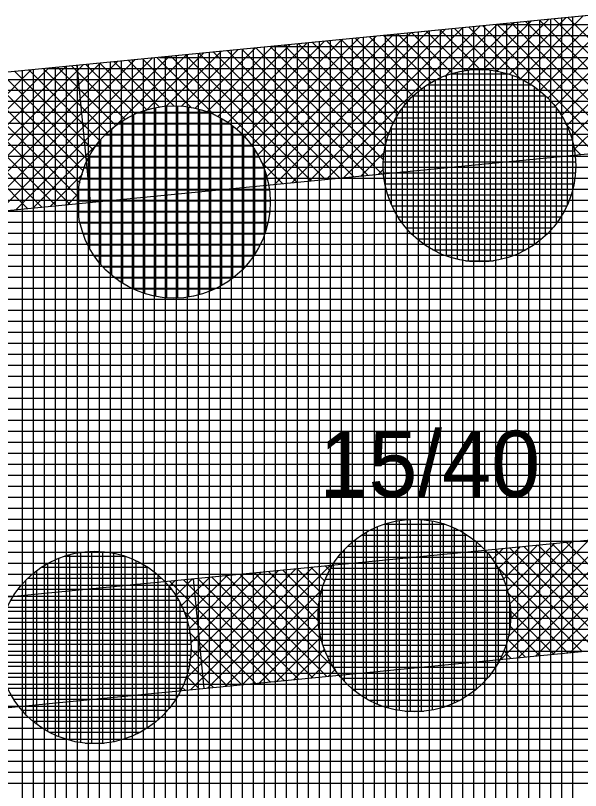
# Model space of a CAD drawing. Extents: x -566461 to -565198, y -1096301 to -1095707.
# Drawn here: x -566346.81 to -566336.54, y -1095854.4 to -1095840.31 of the extents above; entities that cross this region are included whole.
import ezdxf

# ---------------------------------------------------------------- set-up
doc = ezdxf.new("R2010")
doc.units = 0
for name, color, linetype in [('Vrstva 1', 7, 'Continuous'), ('Vrstva 40', 7, 'Continuous'), ('Vrstva 41', 7, 'Continuous'), ('Vrstva 42', 7, 'Continuous'), ('Vrstva 43', 7, 'Continuous'), ('Vrstva 44', 7, 'Continuous')]:
    doc.layers.add(name, color=color, linetype=linetype)

msp = doc.modelspace()

# ---------------------------------------------------------------- linework, layer by layer
at = {"layer": 'Vrstva 1'}
msp.add_line((-566305.22, -1095837.26), (-566355.65, -1095842.19), dxfattribs=at)
at = {"layer": 'Vrstva 41'}
for p, q in [((-566333.984, -1095840.072), (-566336.664, -1095842.752)), ((-566335.551, -1095840.225), (-566337.143, -1095841.817)), ((-566335.238, -1095840.195), (-566337.011, -1095841.967)), ((-566334.924, -1095840.164), (-566336.895, -1095842.134)), ((-566334.611, -1095840.133), (-566336.796, -1095842.318)), ((-566334.297, -1095840.103), (-566336.717, -1095842.523)), ((-566336.805, -1095840.348), (-566337.841, -1095841.383)), ((-566336.492, -1095840.317), (-566337.64, -1095841.465)), ((-566336.178, -1095840.286), (-566337.457, -1095841.565)), ((-566335.865, -1095840.256), (-566337.292, -1095841.683)), ((-566337.03, -1095840.37), (-566334.742, -1095842.658)), ((-566336.772, -1095840.344), (-566334.631, -1095842.486)), ((-566338.373, -1095840.501), (-566341.156, -1095843.285)), ((-566338.059, -1095840.47), (-566339.006, -1095841.417)), ((-566337.746, -1095840.44), (-566338.624, -1095841.318)), ((-566337.432, -1095840.409), (-566338.324, -1095841.301)), ((-566338.318, -1095840.496), (-566336.03, -1095842.784)), ((-566337.119, -1095840.378), (-566338.069, -1095841.328)), ((-566338.06, -1095840.47), (-566335.772, -1095842.758)), ((-566337.803, -1095840.445), (-566335.515, -1095842.733)), ((-566337.545, -1095840.42), (-566335.257, -1095842.708)), ((-566337.287, -1095840.395), (-566334.999, -1095842.683)), ((-566339.94, -1095840.654), (-566342.323, -1095843.037)), ((-566339.627, -1095840.624), (-566342.252, -1095843.249)), ((-566339.313, -1095840.593), (-566342.097, -1095843.377)), ((-566339, -1095840.562), (-566341.783, -1095843.346)), ((-566338.686, -1095840.532), (-566341.47, -1095843.315)), ((-566339.864, -1095840.647), (-566339.069, -1095841.442)), ((-566339.606, -1095840.622), (-566338.86, -1095841.368)), ((-566339.348, -1095840.596), (-566338.627, -1095841.318)), ((-566339.091, -1095840.571), (-566338.363, -1095841.299)), ((-566338.833, -1095840.546), (-566338.048, -1095841.331)), ((-566338.575, -1095840.521), (-566337.622, -1095841.475)), ((-566341.194, -1095840.777), (-566342.798, -1095842.381)), ((-566340.881, -1095840.746), (-566342.654, -1095842.519)), ((-566340.567, -1095840.716), (-566342.525, -1095842.673)), ((-566340.254, -1095840.685), (-566342.415, -1095842.846)), ((-566341.152, -1095840.773), (-566339.836, -1095842.089)), ((-566340.894, -1095840.748), (-566339.716, -1095841.926)), ((-566340.637, -1095840.722), (-566339.58, -1095841.78)), ((-566340.379, -1095840.697), (-566339.427, -1095841.649)), ((-566340.121, -1095840.672), (-566339.257, -1095841.536)), ((-566342.762, -1095840.93), (-566343.799, -1095841.967)), ((-566342.448, -1095840.899), (-566343.551, -1095842.002)), ((-566342.135, -1095840.869), (-566343.333, -1095842.067)), ((-566341.821, -1095840.838), (-566343.137, -1095842.154)), ((-566341.508, -1095840.807), (-566342.959, -1095842.259)), ((-566342.698, -1095840.924), (-566340.41, -1095843.212)), ((-566342.44, -1095840.899), (-566340.152, -1095843.186)), ((-566342.183, -1095840.873), (-566340.116, -1095842.94)), ((-566341.925, -1095840.848), (-566340.086, -1095842.688)), ((-566341.667, -1095840.823), (-566340.023, -1095842.467)), ((-566341.41, -1095840.798), (-566339.939, -1095842.269)), ((-566344.016, -1095841.053), (-566346.799, -1095843.836)), ((-566343.702, -1095841.022), (-566345.056, -1095842.376)), ((-566343.389, -1095840.991), (-566344.433, -1095842.036)), ((-566344.244, -1095841.075), (-566343.195, -1095842.124)), ((-566343.075, -1095840.961), (-566344.083, -1095841.968)), ((-566343.986, -1095841.05), (-566341.698, -1095843.338)), ((-566343.729, -1095841.025), (-566341.441, -1095843.312)), ((-566343.471, -1095840.999), (-566341.183, -1095843.287)), ((-566343.213, -1095840.974), (-566340.925, -1095843.262)), ((-566342.956, -1095840.949), (-566340.668, -1095843.237)), ((-566345.583, -1095841.206), (-566348.367, -1095843.989)), ((-566345.269, -1095841.175), (-566348.053, -1095843.959)), ((-566344.956, -1095841.145), (-566347.74, -1095843.928)), ((-566344.642, -1095841.114), (-566347.426, -1095843.898)), ((-566344.329, -1095841.083), (-566347.113, -1095843.867)), ((-566345.532, -1095841.201), (-566344.627, -1095842.106)), ((-566345.275, -1095841.176), (-566344.418, -1095842.032)), ((-566345.017, -1095841.151), (-566344.186, -1095841.981)), ((-566344.759, -1095841.125), (-566343.924, -1095841.96)), ((-566344.502, -1095841.1), (-566343.61, -1095841.991)), ((-566346.523, -1095841.298), (-566348.794, -1095843.568)), ((-566346.21, -1095841.267), (-566348.698, -1095843.755)), ((-566345.896, -1095841.236), (-566348.624, -1095843.964)), ((-566347.078, -1095841.352), (-566345.492, -1095842.938)), ((-566346.82, -1095841.327), (-566345.39, -1095842.757)), ((-566346.563, -1095841.302), (-566345.27, -1095842.594)), ((-566346.305, -1095841.276), (-566345.134, -1095842.447)), ((-566346.047, -1095841.251), (-566344.983, -1095842.316)), ((-566345.79, -1095841.226), (-566344.814, -1095842.202)), ((-566348.366, -1095841.478), (-566346.079, -1095843.766)), ((-566348.109, -1095841.453), (-566345.821, -1095843.741)), ((-566347.851, -1095841.428), (-566345.665, -1095843.613)), ((-566347.593, -1095841.402), (-566345.635, -1095843.36)), ((-566347.336, -1095841.377), (-566345.576, -1095843.137)), ((-566348.882, -1095841.528), (-566346.594, -1095843.816)), ((-566348.624, -1095841.503), (-566346.336, -1095843.791)), ((-566336.815, -1095842.282), (-566336.288, -1095842.809)), ((-566340.003, -1095842.414), (-566340.843, -1095843.254)), ((-566345.254, -1095842.574), (-566346.486, -1095843.806)), ((-566336.671, -1095842.708), (-566336.545, -1095842.834)), ((-566340.102, -1095842.796), (-566340.529, -1095843.223)), ((-566342.354, -1095842.965), (-566341.956, -1095843.363)), ((-566340.119, -1095843.096), (-566340.216, -1095843.193)), ((-566345.594, -1095843.197), (-566346.172, -1095843.775)), ((-566342.221, -1095843.38), (-566342.214, -1095843.388)), ((-566345.662, -1095843.547), (-566345.859, -1095843.744)), ((-566335.762, -1095849.791), (-566337.989, -1095852.019)), ((-566335.448, -1095849.76), (-566337.676, -1095851.988)), ((-566337.329, -1095849.944), (-566337.95, -1095850.565)), ((-566337.016, -1095849.913), (-566337.88, -1095850.777)), ((-566336.075, -1095849.822), (-566337.866, -1095851.613)), ((-566336.702, -1095849.883), (-566337.833, -1095851.014)), ((-566336.389, -1095849.852), (-566337.827, -1095851.291)), ((-566335.293, -1095849.887), (-566337.362, -1095851.957)), ((-566337.314, -1095849.943), (-566335.483, -1095851.774)), ((-566337.056, -1095849.917), (-566335.225, -1095851.748)), ((-566336.799, -1095849.892), (-566335.427, -1095851.264)), ((-566338.269, -1095850.036), (-566338.278, -1095850.045)), ((-566337.956, -1095850.005), (-566338.15, -1095850.2)), ((-566338.087, -1095850.018), (-566336.256, -1095851.849)), ((-566337.643, -1095849.975), (-566338.041, -1095850.373)), ((-566337.829, -1095849.993), (-566335.998, -1095851.824)), ((-566337.572, -1095849.968), (-566335.741, -1095851.799)), ((-566341.718, -1095850.373), (-566343.732, -1095852.387)), ((-566341.404, -1095850.342), (-566343.632, -1095852.57)), ((-566341.091, -1095850.312), (-566343.318, -1095852.539)), ((-566341.694, -1095850.371), (-566341.25, -1095850.815)), ((-566341.437, -1095850.346), (-566341.183, -1095850.599)), ((-566341.179, -1095850.32), (-566341.095, -1095850.404)), ((-566338.08, -1095850.308), (-566336.514, -1095851.874)), ((-566335.467, -1095850.345), (-566337.049, -1095851.927)), ((-566342.972, -1095850.496), (-566343.72, -1095851.244)), ((-566342.658, -1095850.465), (-566343.661, -1095851.468)), ((-566342.031, -1095850.404), (-566343.652, -1095852.024)), ((-566342.345, -1095850.434), (-566343.632, -1095851.721)), ((-566342.982, -1095850.497), (-566341.152, -1095852.328)), ((-566342.725, -1095850.472), (-566340.995, -1095852.202)), ((-566342.467, -1095850.446), (-566341.237, -1095851.677)), ((-566342.21, -1095850.421), (-566341.294, -1095851.336)), ((-566341.952, -1095850.396), (-566341.292, -1095851.056)), ((-566343.912, -1095850.588), (-566344.023, -1095850.698)), ((-566344.013, -1095850.597), (-566342.182, -1095852.428)), ((-566343.599, -1095850.557), (-566343.904, -1095850.862)), ((-566343.285, -1095850.526), (-566343.802, -1095851.043)), ((-566343.755, -1095850.572), (-566341.925, -1095852.403)), ((-566343.498, -1095850.547), (-566341.667, -1095852.378)), ((-566343.24, -1095850.522), (-566341.409, -1095852.353)), ((-566341.228, -1095850.732), (-566343.005, -1095852.509)), ((-566337.874, -1095850.797), (-566336.771, -1095851.9)), ((-566335.508, -1095850.668), (-566336.735, -1095851.896)), ((-566341.293, -1095851.08), (-566342.691, -1095852.478)), ((-566343.763, -1095851.13), (-566342.44, -1095852.454)), ((-566337.824, -1095851.129), (-566337.029, -1095851.925)), ((-566341.293, -1095851.362), (-566342.378, -1095852.447)), ((-566337.839, -1095851.398), (-566337.287, -1095851.95)), ((-566343.652, -1095851.524), (-566342.698, -1095852.479)), ((-566341.255, -1095851.608), (-566342.065, -1095852.417)), ((-566337.875, -1095851.645), (-566337.544, -1095851.975)), ((-566343.631, -1095851.828), (-566342.955, -1095852.504)), ((-566341.19, -1095851.825), (-566341.751, -1095852.386)), ((-566337.944, -1095851.859), (-566337.802, -1095852)), ((-566341.103, -1095852.021), (-566341.438, -1095852.356)), ((-566343.658, -1095852.084), (-566343.213, -1095852.529)), ((-566340.997, -1095852.198), (-566341.124, -1095852.325)), ((-566343.707, -1095852.317), (-566343.471, -1095852.554)), ((-566343.785, -1095852.523), (-566343.728, -1095852.579)), ((-566346.751, -1095852.86), (-566346.767, -1095852.876))]:
    msp.add_line(p, q, dxfattribs=at)
at = {"layer": 'Vrstva 42'}
for p, q in [((-566345.697, -1095841.217), (-566345.454, -1095843.705)), ((-566343.579, -1095850.555), (-566343.385, -1095852.546))]:
    msp.add_line(p, q, dxfattribs=at)
for points in [[(-566355.65, -1095842.19), (-566355.093, -1095844.647), (-566304.64, -1095839.715), (-566305.22, -1095837.26)], [(-566353.532, -1095851.528), (-566353.085, -1095853.494), (-566302.553, -1095848.555), (-566303.017, -1095846.59)]]:
    msp.add_lwpolyline(points, close=True, dxfattribs=at)
at = {"layer": 'Vrstva 43'}
for p, q in [((-566336.89, -1095840.356), (-566336.89, -1095861.195)), ((-566336.69, -1095840.336), (-566336.69, -1095861.18)), ((-566338.49, -1095840.512), (-566338.49, -1095861.319)), ((-566338.29, -1095840.493), (-566338.29, -1095861.303)), ((-566338.09, -1095840.473), (-566338.09, -1095861.288)), ((-566338.056, -1095840.47), (-566304.463, -1095840.47)), ((-566337.89, -1095840.454), (-566337.89, -1095861.272)), ((-566337.69, -1095840.434), (-566337.69, -1095861.257)), ((-566337.49, -1095840.415), (-566337.49, -1095861.242)), ((-566337.29, -1095840.395), (-566337.29, -1095861.226)), ((-566337.09, -1095840.376), (-566337.09, -1095861.211)), ((-566339.89, -1095840.649), (-566339.89, -1095861.427)), ((-566339.69, -1095840.63), (-566339.69, -1095861.411)), ((-566339.49, -1095840.61), (-566339.49, -1095861.396)), ((-566339.29, -1095840.591), (-566339.29, -1095861.38)), ((-566339.09, -1095840.571), (-566339.09, -1095861.365)), ((-566338.89, -1095840.552), (-566338.89, -1095861.35)), ((-566338.69, -1095840.532), (-566338.69, -1095861.334)), ((-566341.29, -1095840.786), (-566341.29, -1095861.535)), ((-566341.09, -1095840.767), (-566341.09, -1095861.519)), ((-566340.89, -1095840.747), (-566340.89, -1095861.504)), ((-566340.69, -1095840.728), (-566340.69, -1095861.488)), ((-566340.49, -1095840.708), (-566340.49, -1095861.473)), ((-566340.29, -1095840.688), (-566340.29, -1095861.457)), ((-566340.102, -1095840.67), (-566304.416, -1095840.67)), ((-566340.09, -1095840.669), (-566340.09, -1095861.442)), ((-566342.69, -1095840.923), (-566342.69, -1095861.642)), ((-566342.49, -1095840.903), (-566342.49, -1095861.627)), ((-566342.29, -1095840.884), (-566342.29, -1095861.612)), ((-566342.147, -1095840.87), (-566304.368, -1095840.87)), ((-566342.09, -1095840.864), (-566342.09, -1095861.596)), ((-566341.89, -1095840.845), (-566341.89, -1095861.581)), ((-566341.69, -1095840.825), (-566341.69, -1095861.565)), ((-566341.49, -1095840.806), (-566341.49, -1095861.55)), ((-566344.193, -1095841.07), (-566304.321, -1095841.07)), ((-566344.09, -1095841.06), (-566344.09, -1095861.75)), ((-566343.89, -1095841.04), (-566343.89, -1095861.735)), ((-566343.69, -1095841.021), (-566343.69, -1095861.72)), ((-566343.49, -1095841.001), (-566343.49, -1095861.704)), ((-566343.29, -1095840.982), (-566343.29, -1095861.689)), ((-566343.09, -1095840.962), (-566343.09, -1095861.673)), ((-566342.89, -1095840.943), (-566342.89, -1095861.658)), ((-566345.69, -1095841.216), (-566345.69, -1095861.874)), ((-566345.49, -1095841.197), (-566345.49, -1095861.858)), ((-566345.29, -1095841.177), (-566345.29, -1095861.843)), ((-566345.09, -1095841.158), (-566345.09, -1095861.827)), ((-566344.89, -1095841.138), (-566344.89, -1095861.812)), ((-566344.69, -1095841.119), (-566344.69, -1095861.797)), ((-566344.49, -1095841.099), (-566344.49, -1095861.781)), ((-566344.29, -1095841.079), (-566344.29, -1095861.766)), ((-566346.69, -1095841.314), (-566346.69, -1095861.951)), ((-566346.49, -1095841.295), (-566346.49, -1095861.935)), ((-566346.29, -1095841.275), (-566346.29, -1095861.92)), ((-566346.239, -1095841.27), (-566304.274, -1095841.27)), ((-566346.09, -1095841.255), (-566346.09, -1095861.905)), ((-566345.89, -1095841.236), (-566345.89, -1095861.889)), ((-566348.285, -1095841.47), (-566304.227, -1095841.47)), ((-566350.331, -1095841.67), (-566304.18, -1095841.67)), ((-566352.377, -1095841.87), (-566304.132, -1095841.87)), ((-566354.423, -1095842.07), (-566304.085, -1095842.07)), ((-566355.632, -1095842.27), (-566304.038, -1095842.27)), ((-566355.586, -1095842.47), (-566303.991, -1095842.47)), ((-566355.541, -1095842.67), (-566303.944, -1095842.67)), ((-566355.496, -1095842.87), (-566303.897, -1095842.87)), ((-566355.45, -1095843.07), (-566303.849, -1095843.07)), ((-566355.405, -1095843.27), (-566303.802, -1095843.27)), ((-566355.36, -1095843.47), (-566303.755, -1095843.47)), ((-566355.314, -1095843.67), (-566303.708, -1095843.67)), ((-566355.269, -1095843.87), (-566303.661, -1095843.87)), ((-566355.223, -1095844.07), (-566303.613, -1095844.07)), ((-566355.178, -1095844.27), (-566303.566, -1095844.27)), ((-566355.133, -1095844.47), (-566303.519, -1095844.47)), ((-566355.087, -1095844.67), (-566303.472, -1095844.67)), ((-566355.042, -1095844.87), (-566303.425, -1095844.87)), ((-566354.997, -1095845.07), (-566303.378, -1095845.07)), ((-566354.951, -1095845.27), (-566303.33, -1095845.27)), ((-566354.906, -1095845.47), (-566303.283, -1095845.47)), ((-566354.861, -1095845.67), (-566303.236, -1095845.67)), ((-566354.815, -1095845.87), (-566303.189, -1095845.87)), ((-566354.77, -1095846.07), (-566303.142, -1095846.07)), ((-566354.724, -1095846.27), (-566303.094, -1095846.27)), ((-566354.679, -1095846.47), (-566303.047, -1095846.47)), ((-566354.634, -1095846.67), (-566303, -1095846.67)), ((-566354.588, -1095846.87), (-566302.953, -1095846.87)), ((-566354.543, -1095847.07), (-566302.906, -1095847.07)), ((-566354.498, -1095847.27), (-566302.859, -1095847.27)), ((-566354.452, -1095847.47), (-566302.811, -1095847.47)), ((-566354.407, -1095847.67), (-566302.764, -1095847.67)), ((-566354.361, -1095847.87), (-566302.717, -1095847.87)), ((-566354.316, -1095848.07), (-566302.67, -1095848.07)), ((-566354.271, -1095848.27), (-566302.623, -1095848.27)), ((-566354.225, -1095848.47), (-566302.575, -1095848.47)), ((-566354.18, -1095848.67), (-566302.528, -1095848.67)), ((-566354.135, -1095848.87), (-566302.481, -1095848.87)), ((-566354.089, -1095849.07), (-566302.434, -1095849.07)), ((-566354.044, -1095849.27), (-566302.387, -1095849.27)), ((-566353.998, -1095849.47), (-566302.34, -1095849.47)), ((-566353.953, -1095849.67), (-566302.292, -1095849.67)), ((-566353.908, -1095849.87), (-566302.245, -1095849.87)), ((-566353.862, -1095850.07), (-566302.198, -1095850.07)), ((-566353.817, -1095850.27), (-566302.151, -1095850.27)), ((-566353.772, -1095850.47), (-566302.104, -1095850.47)), ((-566353.726, -1095850.67), (-566302.056, -1095850.67)), ((-566353.681, -1095850.87), (-566302.009, -1095850.87)), ((-566353.635, -1095851.07), (-566301.962, -1095851.07)), ((-566353.59, -1095851.27), (-566301.915, -1095851.27)), ((-566353.545, -1095851.47), (-566301.868, -1095851.47)), ((-566353.499, -1095851.67), (-566301.821, -1095851.67)), ((-566353.454, -1095851.87), (-566301.773, -1095851.87)), ((-566353.409, -1095852.07), (-566301.726, -1095852.07)), ((-566353.363, -1095852.27), (-566301.679, -1095852.27)), ((-566353.318, -1095852.47), (-566301.632, -1095852.47)), ((-566353.272, -1095852.67), (-566301.585, -1095852.67)), ((-566353.227, -1095852.87), (-566301.537, -1095852.87)), ((-566353.182, -1095853.07), (-566301.49, -1095853.07)), ((-566353.136, -1095853.27), (-566301.443, -1095853.27)), ((-566353.091, -1095853.47), (-566301.396, -1095853.47)), ((-566353.046, -1095853.67), (-566301.349, -1095853.67)), ((-566353, -1095853.87), (-566301.302, -1095853.87)), ((-566352.955, -1095854.07), (-566301.254, -1095854.07)), ((-566352.909, -1095854.27), (-566301.207, -1095854.27))]:
    msp.add_line(p, q, dxfattribs=at)
msp.add_lwpolyline([(-566355.65, -1095842.19), (-566351.09, -1095862.29), (-566300.24, -1095858.37), (-566305.22, -1095837.26)], close=True, dxfattribs=at)
at = {"layer": 'Vrstva 44'}
for p, q in [((-566338.78, -1095844.743), (-566338.78, -1095841.338)), ((-566338.58, -1095844.778), (-566338.58, -1095841.303)), ((-566338.38, -1095844.788), (-566338.38, -1095841.291)), ((-566338.18, -1095844.777), (-566338.18, -1095841.302)), ((-566337.98, -1095844.742), (-566337.98, -1095841.338)), ((-566339.18, -1095844.596), (-566339.18, -1095841.484)), ((-566338.98, -1095844.682), (-566338.98, -1095841.397)), ((-566338.898, -1095841.37), (-566337.858, -1095841.37)), ((-566337.78, -1095844.684), (-566337.78, -1095841.398)), ((-566337.58, -1095844.595), (-566337.58, -1095841.485)), ((-566339.38, -1095844.474), (-566339.38, -1095841.606)), ((-566339.328, -1095841.57), (-566337.432, -1095841.57)), ((-566337.38, -1095844.474), (-566337.38, -1095841.606)), ((-566339.583, -1095841.77), (-566337.178, -1095841.77)), ((-566339.58, -1095844.313), (-566339.58, -1095841.767)), ((-566337.18, -1095844.312), (-566337.18, -1095841.768)), ((-566344.46, -1095845.366), (-566344.46, -1095842.034)), ((-566344.26, -1095845.417), (-566344.26, -1095841.982)), ((-566344.06, -1095845.443), (-566344.06, -1095841.955)), ((-566343.86, -1095845.447), (-566343.86, -1095841.953)), ((-566343.66, -1095845.428), (-566343.66, -1095841.973)), ((-566343.46, -1095845.385), (-566343.46, -1095842.016)), ((-566339.78, -1095844.087), (-566339.78, -1095841.992)), ((-566339.763, -1095841.97), (-566336.998, -1095841.97)), ((-566336.98, -1095844.09), (-566336.98, -1095841.993)), ((-566344.66, -1095845.288), (-566344.66, -1095842.112)), ((-566344.589, -1095842.08), (-566343.27, -1095842.08)), ((-566343.26, -1095845.315), (-566343.26, -1095842.084)), ((-566343.06, -1095845.217), (-566343.06, -1095842.184)), ((-566339.897, -1095842.17), (-566336.863, -1095842.17)), ((-566344.95, -1095842.28), (-566342.91, -1095842.28)), ((-566344.86, -1095845.181), (-566344.86, -1095842.218)), ((-566342.86, -1095845.083), (-566342.86, -1095842.317)), ((-566339.98, -1095843.748), (-566339.98, -1095842.335)), ((-566336.78, -1095843.744), (-566336.78, -1095842.332)), ((-566345.182, -1095842.48), (-566342.677, -1095842.48)), ((-566345.06, -1095845.034), (-566345.06, -1095842.366)), ((-566339.995, -1095842.37), (-566336.765, -1095842.37)), ((-566345.26, -1095844.837), (-566345.26, -1095842.564)), ((-566342.66, -1095844.902), (-566342.66, -1095842.499)), ((-566340.064, -1095842.57), (-566336.696, -1095842.57)), ((-566345.351, -1095842.68), (-566342.51, -1095842.68)), ((-566342.46, -1095844.647), (-566342.46, -1095842.754)), ((-566345.474, -1095842.88), (-566342.385, -1095842.88)), ((-566345.46, -1095844.548), (-566345.46, -1095842.854)), ((-566340.109, -1095842.77), (-566336.653, -1095842.77)), ((-566340.128, -1095842.97), (-566336.632, -1095842.97)), ((-566345.565, -1095843.08), (-566342.296, -1095843.08)), ((-566342.26, -1095844.217), (-566342.26, -1095843.18)), ((-566340.123, -1095843.17), (-566336.635, -1095843.17)), ((-566345.629, -1095843.28), (-566342.233, -1095843.28)), ((-566345.66, -1095843.958), (-566345.66, -1095843.437)), ((-566340.097, -1095843.37), (-566336.663, -1095843.37)), ((-566345.665, -1095843.48), (-566342.194, -1095843.48)), ((-566340.046, -1095843.57), (-566336.714, -1095843.57)), ((-566345.678, -1095843.68), (-566342.181, -1095843.68)), ((-566345.669, -1095843.88), (-566342.191, -1095843.88)), ((-566339.97, -1095843.77), (-566336.791, -1095843.77)), ((-566339.86, -1095843.97), (-566336.899, -1095843.97)), ((-566345.637, -1095844.08), (-566342.224, -1095844.08)), ((-566339.715, -1095844.17), (-566337.046, -1095844.17)), ((-566345.58, -1095844.28), (-566342.28, -1095844.28)), ((-566339.514, -1095844.37), (-566337.245, -1095844.37)), ((-566345.494, -1095844.48), (-566342.364, -1095844.48)), ((-566339.226, -1095844.57), (-566337.535, -1095844.57)), ((-566345.378, -1095844.68), (-566342.483, -1095844.68)), ((-566345.22, -1095844.88), (-566342.638, -1095844.88)), ((-566338.634, -1095844.77), (-566338.124, -1095844.77)), ((-566345.005, -1095845.08), (-566342.856, -1095845.08)), ((-566344.678, -1095845.28), (-566343.179, -1095845.28)), ((-566339.83, -1095852.947), (-566339.83, -1095849.492)), ((-566339.63, -1095852.968), (-566339.63, -1095849.473)), ((-566339.43, -1095852.965), (-566339.43, -1095849.477)), ((-566339.23, -1095852.937), (-566339.23, -1095849.503)), ((-566340.23, -1095852.836), (-566340.23, -1095849.605)), ((-566340.108, -1095849.56), (-566339.01, -1095849.56)), ((-566340.03, -1095852.905), (-566340.03, -1095849.534)), ((-566339.03, -1095852.886), (-566339.03, -1095849.553)), ((-566338.83, -1095852.809), (-566338.83, -1095849.632)), ((-566340.522, -1095849.76), (-566338.596, -1095849.76)), ((-566340.43, -1095852.736), (-566340.43, -1095849.704)), ((-566338.63, -1095852.701), (-566338.63, -1095849.739)), ((-566340.63, -1095852.604), (-566340.63, -1095849.835)), ((-566338.43, -1095852.554), (-566338.43, -1095849.885)), ((-566345.62, -1095853.531), (-566345.62, -1095850.07)), ((-566345.42, -1095853.549), (-566345.42, -1095850.053)), ((-566345.22, -1095853.542), (-566345.22, -1095850.058)), ((-566345.02, -1095853.513), (-566345.02, -1095850.086)), ((-566340.83, -1095852.421), (-566340.83, -1095850.019)), ((-566340.773, -1095849.96), (-566338.347, -1095849.96)), ((-566338.23, -1095852.355), (-566338.23, -1095850.084)), ((-566346.02, -1095853.425), (-566346.02, -1095850.176)), ((-566345.918, -1095850.14), (-566344.82, -1095850.14)), ((-566345.82, -1095853.49), (-566345.82, -1095850.11)), ((-566344.82, -1095853.459), (-566344.82, -1095850.14)), ((-566344.62, -1095853.381), (-566344.62, -1095850.221)), ((-566340.951, -1095850.16), (-566338.17, -1095850.16)), ((-566346.332, -1095850.34), (-566344.406, -1095850.34)), ((-566346.22, -1095853.328), (-566346.22, -1095850.273)), ((-566344.42, -1095853.268), (-566344.42, -1095850.331)), ((-566341.083, -1095850.36), (-566338.037, -1095850.36)), ((-566341.03, -1095852.166), (-566341.03, -1095850.274)), ((-566338.03, -1095852.065), (-566338.03, -1095850.371)), ((-566346.42, -1095853.198), (-566346.42, -1095850.401)), ((-566344.22, -1095853.117), (-566344.22, -1095850.483)), ((-566346.62, -1095853.022), (-566346.62, -1095850.578)), ((-566346.583, -1095850.54), (-566344.157, -1095850.54)), ((-566341.179, -1095850.56), (-566337.941, -1095850.56)), ((-566346.761, -1095850.74), (-566343.98, -1095850.74)), ((-566344.02, -1095852.91), (-566344.02, -1095850.687)), ((-566341.247, -1095850.76), (-566337.874, -1095850.76)), ((-566341.23, -1095851.738), (-566341.23, -1095850.704)), ((-566346.893, -1095850.94), (-566343.847, -1095850.94)), ((-566343.82, -1095852.609), (-566343.82, -1095850.991)), ((-566341.29, -1095850.96), (-566337.831, -1095850.96)), ((-566337.83, -1095851.476), (-566337.83, -1095850.966)), ((-566346.989, -1095851.14), (-566343.751, -1095851.14)), ((-566341.308, -1095851.16), (-566337.812, -1095851.16)), ((-566347.057, -1095851.34), (-566343.684, -1095851.34)), ((-566341.302, -1095851.36), (-566337.816, -1095851.36)), ((-566347.1, -1095851.54), (-566343.641, -1095851.54)), ((-566341.275, -1095851.56), (-566337.845, -1095851.56)), ((-566347.118, -1095851.74), (-566343.622, -1095851.74)), ((-566341.224, -1095851.76), (-566337.897, -1095851.76)), ((-566347.112, -1095851.94), (-566343.626, -1095851.94)), ((-566341.145, -1095851.96), (-566337.975, -1095851.96)), ((-566347.085, -1095852.14), (-566343.655, -1095852.14)), ((-566341.034, -1095852.16), (-566338.085, -1095852.16)), ((-566347.034, -1095852.34), (-566343.707, -1095852.34)), ((-566340.888, -1095852.36), (-566338.234, -1095852.36)), ((-566346.955, -1095852.54), (-566343.785, -1095852.54)), ((-566340.683, -1095852.56), (-566338.437, -1095852.56)), ((-566346.844, -1095852.74), (-566343.895, -1095852.74)), ((-566340.389, -1095852.76), (-566338.733, -1095852.76)), ((-566346.698, -1095852.94), (-566344.044, -1095852.94)), ((-566339.732, -1095852.96), (-566339.39, -1095852.96)), ((-566346.493, -1095853.14), (-566344.247, -1095853.14)), ((-566346.199, -1095853.34), (-566344.543, -1095853.34)), ((-566345.542, -1095853.54), (-566345.2, -1095853.54))]:
    msp.add_line(p, q, dxfattribs=at)
for centre in [(-566338.38, -1095843.04), (-566343.93, -1095843.7), (-566339.56, -1095851.22), (-566345.37, -1095851.8)]:
    msp.add_circle(centre, 1.75, dxfattribs=at)

# ---------------------------------------------------------------- texts
at = {"layer": 'Vrstva 40'}
msp.add_text('15/40', height=1.2, dxfattribs=at).set_placement((-566341.29, -1095849.06))

doc.saveas('drawing.dxf')
